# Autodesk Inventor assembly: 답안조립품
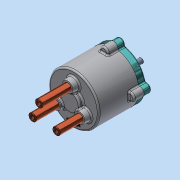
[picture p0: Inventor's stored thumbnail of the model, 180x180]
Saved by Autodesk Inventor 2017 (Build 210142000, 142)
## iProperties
Part Number: 답안조립품
Material: 일반
Document SubType Name: Assembly
Designer: MRC
Mass: 1236.63 g
Surface Area: 1770.12 cm^2
Volume: 433.787 cm^3
Density: 2.85077 g/cm^3
Author: MRC
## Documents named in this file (14)
- C:\Users\MRC\Desktop\610708V1014\답안조립품.iam
- C:\Users\MRC\Desktop\610708V1014\본체.ipt
- C:\Users\MRC\Desktop\610708V1014\멈춤링 10 x 1.ipt
- C:\Users\MRC\Desktop\610708V1014\멈춤링 22 x 1.2.ipt
- C:\Users\MRC\Desktop\610708V1014\메인 축.ipt
- C:\Users\MRC\Desktop\610708V1014\베어링 NA 4900.ipt
- C:\Users\MRC\Desktop\610708V1014\볼트 M5.ipt
- C:\Users\MRC\Desktop\610708V1014\슬라이드 축.ipt
- C:\Users\MRC\Desktop\610708V1014\오일실.ipt
- C:\Users\MRC\Desktop\610708V1014\커버.ipt
- C:\Users\MRC\Desktop\610708V1014\판캠.ipt
- C:\Users\MRC\Desktop\610708V1014\가변스프링.ipt
- C:\Users\MRC\Desktop\610708V1014\가변스프링2.ipt
- C:\Users\MRC\Desktop\610708V1014\가변스프링3.ipt
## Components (3 placed, 3 different names)
1. 가변스프링:3
2. 가변스프링2:1
3. 가변스프링3:1
